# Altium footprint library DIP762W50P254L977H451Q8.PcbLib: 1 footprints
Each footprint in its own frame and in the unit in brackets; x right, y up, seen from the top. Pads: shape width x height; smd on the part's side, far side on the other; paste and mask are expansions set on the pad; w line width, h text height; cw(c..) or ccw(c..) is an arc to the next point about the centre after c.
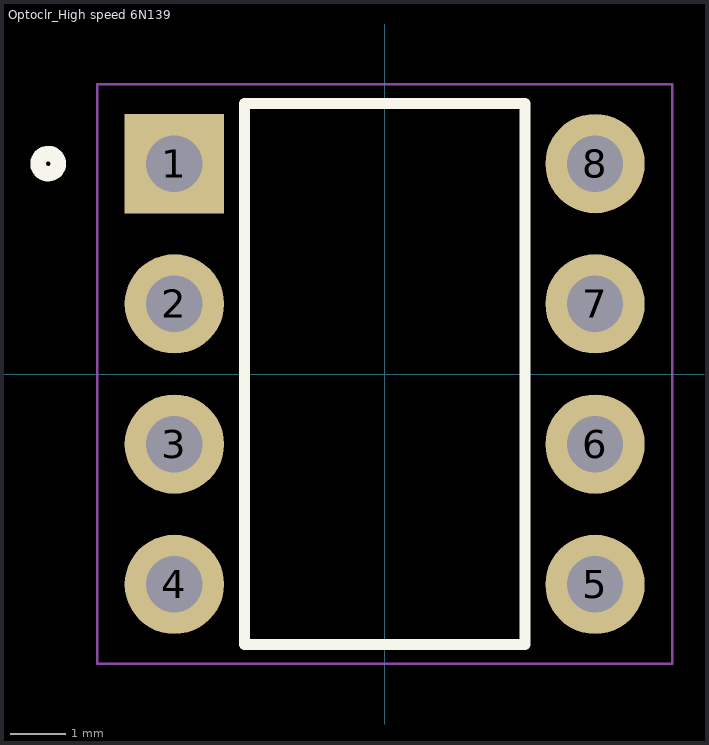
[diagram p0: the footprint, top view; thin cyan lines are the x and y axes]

## Optoclr_High speed 6N139 [mm] "Optoclr_High speed 6N139 DIP-8"
pads (8):
  rect 1.8x1.8 hole 1.02: 1(-3.81,3.81)
  round 1.8 hole 1.02: 2(-3.81,1.27) 3(-3.81,-1.27) 4(-3.81,-3.81) 5(3.81,-3.81) 6(3.81,-1.27) 7(3.81,1.27) 8(3.81,3.81)
Top Overlay:
  circle w0.2: c-6.096,3.81 r0.141
  circle w0.2: c-6.096,3.81 r0.224
  lines w0.2: -2.54,-4.9 2.54,-4.9 2.54,4.9 -2.54,4.9 -2.54,-4.9
Courtyard Top:
  lines w0.05: -5.207,-5.25 5.207,-5.25 5.207,5.25 -5.207,5.25 -5.207,-5.25
3D body "step_temp.STEP": height 5.08, standoff -3.9, extent -3.96,-4.828 3.96,4.828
